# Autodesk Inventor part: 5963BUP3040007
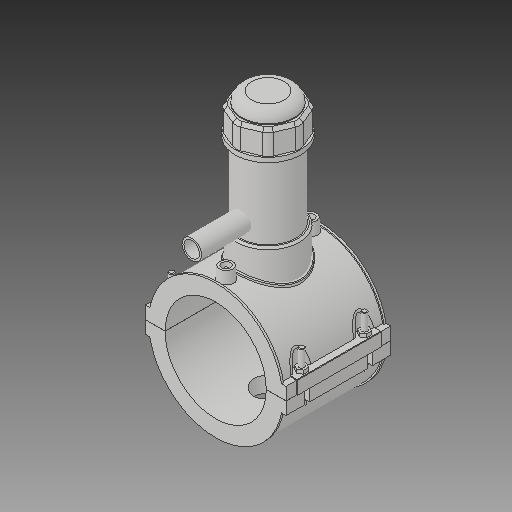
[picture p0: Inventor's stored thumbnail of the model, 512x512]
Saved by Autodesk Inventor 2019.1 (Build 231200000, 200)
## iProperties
Created: 2017-07
Part Number: 5963BUP3040007
Material: Generic
Description: PLASSON TAPPING SADDLE 4''IPS x 3/4''CTS
Document SubType Name: Modeling
Designer: KIM
Density: 1 g/cm^3
Appearance: Default
Author: KIM
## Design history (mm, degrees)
derived "5963BBP_5963BUP.ipt"
feature "Solid1::5963BBP_5963BUP.ipt"
feature "Solid2::5963BBP_5963BUP.ipt"
feature "Solid3::5963BBP_5963BUP.ipt"
tag "TaggingFeature1"
body "Solid1"
body "Solid2"
body "Solid3"
other parameters: "d0" = 114.1, "d2" = 159.004, "d3" = 28.525, "d4" = 118.11, "d5" = 0, "d6" = 0.1, "d8" = 0, "d19" = 6, "d20" = 6, "d21" = 70.866, "d23" = 0, "d24" = 35.433, "d26" = 0, "d27" = 3, "d28" = 3, "d29" = 3, "d30" = 38.03333, "d31" = 6, "d32" = 0, "d33" = 0, "d34" = 0.6, "d40" = 77.1316, "d41" = 74.165, "d43" = 0, "d45" = 0, "d47" = 145.031, "d70" = 15, "d72" = 0, "d73" = 6, "d75" = 5, "d76" = 0, "d77" = 5.705, "d78" = 87.05, "d79" = 15, "d80" = 47.244, "d82" = 5 deg, "d84" = 4, "d85" = 14, "d86" = 0, "d87" = 3, "d88" = 0, "d89" = 1, "d90" = 1, "d91" = 94.488, "d92" = 0, "d93" = 0.5, "d94" = 60.05263, "d96" = 151.2966, "d97" = 2.3622, "d98" = 0, "d102" = 1.141, "d120" = 140 deg, "d121" = 24.228, "d122" = 20 deg, "d123" = 296.66, "d124" = 88.998, "d126" = 0, "d143" = 117.523, "d145" = 26.33077, "d149" = 1.7115, "d150" = 28.96385, "d153" = 118.11, "d154" = 0, "d156" = 74.165, "d157" = 160 deg, "d159" = 6.846, "d161" = 1.7115, "d162" = 70.866, "d163" = 0, "d164" = 57.05, "d167" = 11.41, "d168" = 72.3561, "d170" = 3.2805, "d172" = 0, "d173" = 1, "d175" = 57.05, "d176" = 20 deg, "d177" = 7.987, "d178" = 34.23, "d180" = 0, "d183" = 13.692, "d184" = 6.3896, "d185" = 38.38575, "d186" = 38.38575, "d187" = 74.165, "d188" = 10.269, "d189" = 7.987, "d190" = 0, "d191" = 111.2475, "d193" = 6.9984, "d194" = 4.13385, "d195" = 90 deg, "d197" = 0, "d199" = 0, "d200" = 17.115, "d202" = 0, "d203" = 177.038, "d204" = 70.45675, "d205" = 51.9155, "d206" = 63.04025, "d207" = 132.7785, "d208" = 138.08964, "d209" = 164.64534, "d210" = 63.7819, "d211" = 74.165, "d212" = 59.332, "d213" = 48.5766, "d216" = 0, "d217" = 11.41, "d218" = 11.41, "d219" = 2.282, "d222" = 114.1, "d224" = 0, "d225" = 65.024, "d226" = 22.1, "d227" = 17.68, "d228" = 86.106, "d230" = 3.423, "d_" = 114.1, "B_" = 159.004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
